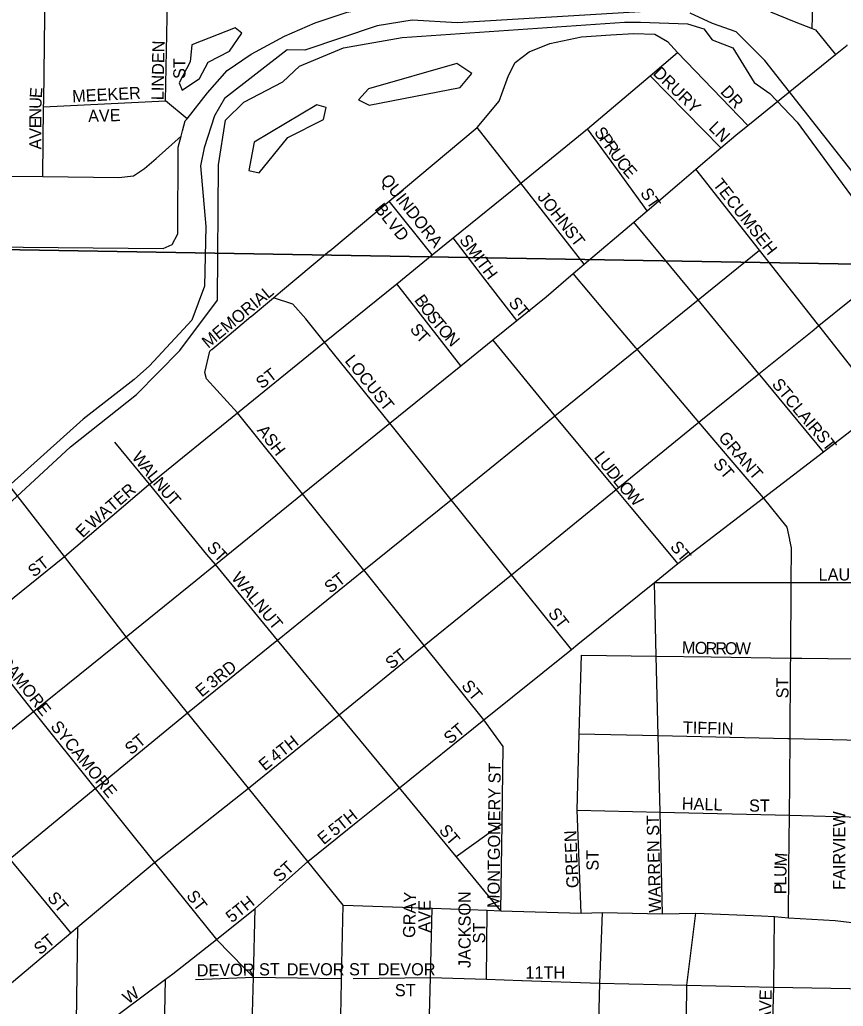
# Model space of a CAD drawing. Extents: x -784 to 1375, y -225 to 440.
# Drawn here: x 295.68 to 308.9, y 352.51 to 368.36 of the extents above; entities that cross this region are included whole.
import ezdxf

# ---------------------------------------------------------------- set-up
doc = ezdxf.new("R2010")
doc.units = 0
for name, color, linetype in [('GM_X_City_Street', 7, 'Continuous'), ('GM_X_City_Street_Text', 7, 'Continuous'), ('GM_X_Major_River', 7, 'Continuous'), ('GM_X_Minor_Lake', 7, 'Continuous'), ('GM_X_Section', 7, 'Continuous'), ('GM_X_State_Route', 7, 'Continuous')]:
    doc.layers.add(name, color=color, linetype=linetype)

msp = doc.modelspace()

# ---------------------------------------------------------------- linework, layer by layer
at = {"layer": 'GM_X_City_Street'}
for points in [[(308.402, 368.215), (308.442, 369.57), (308.493, 371.283), (308.546, 373.085)], [(296.062, 367.039), (296.08, 368.416), (296.099, 369.84), (296.099, 369.84)], [(298.364, 366.766), (298.018, 367.055), (298.043, 368.394), (298.046, 368.496), (298.079, 369.827)], [(298.294, 366.575), (298.336, 366.731), (298.364, 366.766), (298.695, 367.183), (299.011, 367.541), (299.395, 367.804), (299.928, 368.093), (300.42, 368.306), (300.934, 368.478), (301.391, 368.566), (301.904, 368.699), (302.405, 368.699), (302.976, 368.674), (303.39, 368.669), (303.86, 368.662), (304.548, 368.706), (304.949, 368.752), (305.288, 368.791), (306.151, 368.732), (307.184, 368.724)], [(307.733, 368.484), (308.114, 368.327), (308.402, 368.215), (308.457, 368.194), (308.777, 367.798)], [(308.429, 363.378), (308.434, 363.382), (308.511, 363.444), (311.105, 365.533), (314.482, 368.251)], [(300.654, 364.645), (300.655, 364.646), (301.609, 365.444), (303.022, 366.626), (303.377, 367.048), (303.528, 367.46), (303.635, 367.669), (303.859, 367.844), (304.193, 367.977), (304.698, 368.083), (305.17, 368.112), (305.54, 368.135), (305.876, 368.123), (306.079, 368.008), (306.24, 367.829), (307.368, 366.657)], [(304.798, 366.603), (305.801, 367.456), (306.24, 367.829)], [(306.938, 366.298), (305.801, 367.456)], [(296.046, 365.838), (296.061, 366.958), (296.062, 367.038), (296.062, 367.039)], [(296.061, 366.958), (298.018, 367.055)], [(297.775, 360.907), (299.175, 362.043), (300.574, 363.177), (301.733, 364.117), (302.303, 364.58), (302.637, 364.851), (303.723, 365.732), (304.798, 366.603)], [(303.76, 365.685), (303.723, 365.732), (303.022, 366.626)], [(305.275, 365.945), (304.798, 366.603)], [(293.48, 364.725), (297.983, 364.681), (298.126, 364.747), (298.217, 364.916), (298.222, 366.312), (298.27, 366.488), (298.293, 366.571), (298.294, 366.575)], [(294.649, 365.855), (294.701, 365.854), (294.841, 365.852), (296.046, 365.838), (297.267, 365.824), (297.503, 365.848), (297.679, 365.968), (297.871, 366.126), (298.27, 366.488)], [(308.491, 363.47), (308.491, 363.47), (307.56, 364.654), (306.537, 365.956)], [(305.751, 365.287), (305.275, 365.945), (305.275, 365.945)], [(304.744, 364.429), (303.76, 365.685), (303.76, 365.685)], [(302.303, 364.58), (301.609, 365.444)], [(307.061, 363.261), (306.571, 363.855), (305.538, 365.106)], [(303.149, 364.188), (302.637, 364.851)], [(299.808, 358.384), (299.818, 358.392), (301.204, 359.513), (302.605, 360.647), (304.271, 361.994), (305.592, 363.063), (306.571, 363.855), (307.56, 364.654)], [(299.864, 363.984), (299.866, 363.986), (300.654, 364.645)], [(305.07, 363.681), (304.566, 364.278)], [(302.246, 363.457), (301.733, 364.117)], [(303.66, 363.526), (303.149, 364.188), (303.149, 364.188)], [(299.391, 363.587), (299.393, 363.589), (299.754, 363.891), (299.864, 363.984)], [(300.628, 363.109), (300.626, 363.112), (300.574, 363.177), (300.273, 363.552), (300.061, 363.786), (299.754, 363.891)], [(298.759, 363.059), (298.762, 363.061), (299.391, 363.587)], [(305.574, 363.084), (305.07, 363.681), (305.07, 363.681)], [(302.759, 362.796), (302.246, 363.457), (302.246, 363.457)], [(309.533, 362.144), (308.511, 363.444), (308.491, 363.47)], [(300.81, 357.19), (302.175, 358.302), (303.573, 359.441), (305.255, 360.81), (306.582, 361.891), (306.618, 361.92), (307.549, 362.67), (308.429, 363.378)], [(307.569, 362.645), (307.549, 362.67), (307.061, 363.261), (307.061, 363.261)], [(304.536, 358.242), (303.573, 359.441), (302.605, 360.647), (301.62, 361.874), (300.628, 363.109)], [(304.259, 362.01), (303.276, 363.215)], [(299.175, 362.043), (298.677, 362.59), (298.649, 362.692), (298.73, 363.035), (298.759, 363.059)], [(306.582, 361.891), (305.592, 363.063), (305.574, 363.084), (305.574, 363.084)], [(308.584, 361.415), (307.569, 362.645), (307.569, 362.645)], [(301.217, 359.497), (301.204, 359.513), (300.22, 360.739), (299.175, 362.043)], [(305.501, 360.516), (305.496, 360.521), (305.255, 360.81), (304.271, 361.994), (304.259, 362.01), (304.259, 362.01)], [(304.642, 358.327), (305.871, 359.317), (306.248, 359.621), (307.622, 360.677), (308.584, 361.415), (309.147, 361.848), (309.533, 362.144)], [(307.102, 361.284), (306.582, 361.891)], [(297.609, 361.078), (297.609, 361.078), (297.205, 361.569)], [(307.622, 360.677), (307.102, 361.284), (307.102, 361.284)], [(298.819, 359.604), (298.684, 359.768), (297.759, 360.894), (297.609, 361.078)], [(296.399, 359.735), (297.746, 360.884), (297.759, 360.894), (297.775, 360.907)], [(308.045, 360.005), (308.002, 360.205), (307.622, 360.677)], [(306.248, 359.621), (305.501, 360.516)], [(308.057, 357.982), (308.058, 358.102), (308.068, 359.317), (308.073, 359.874), (308.046, 359.998), (308.045, 360.005)], [(294.796, 358.441), (294.886, 358.517), (296.399, 359.735)], [(303.404, 354.044), (302.685, 354.916), (301.775, 356.019), (300.81, 357.19), (299.818, 358.392), (298.819, 359.604)], [(302.11, 358.384), (301.217, 359.497), (301.217, 359.497)], [(305.871, 359.317), (307.97, 359.317), (307.97, 359.317)], [(306, 353.991), (305.96, 355.625), (305.931, 356.858), (305.9, 358.132), (305.871, 359.317)], [(307.97, 359.317), (308.068, 359.317), (309.859, 359.316)], [(295.898, 357.244), (294.886, 358.517)], [(298.374, 357.224), (299.808, 358.384)], [(303.131, 357.111), (302.175, 358.302), (302.11, 358.384), (302.11, 358.384)], [(301.75, 355.999), (301.775, 356.019), (303.131, 357.111), (304.536, 358.242), (304.642, 358.327), (304.642, 358.327)], [(304.691, 354.005), (304.627, 355.657), (304.663, 356.887), (304.7, 358.148)], [(304.7, 358.148), (305.9, 358.132), (306.78, 358.12), (306.78, 358.12)], [(306.78, 358.12), (308.058, 358.102), (308.237, 358.1), (308.237, 358.1)], [(308.237, 358.1), (310.733, 358.066)], [(308.042, 356.159), (308.048, 356.81), (308.057, 357.948), (308.057, 357.982)], [(296.496, 353.687), (295.518, 354.877), (294.501, 356.117), (293.494, 357.343)], [(295.898, 357.244), (296.891, 356.006), (297.844, 354.818), (298.835, 353.583), (299.286, 353.123)], [(296.96, 356.062), (298.374, 357.224)], [(299.354, 356.01), (300.81, 357.19)], [(303.404, 354.044), (303.424, 355.444), (303.441, 356.682), (303.131, 357.111)], [(304.663, 356.887), (305.931, 356.858), (308.014, 356.811), (308.014, 356.811)], [(308.014, 356.811), (308.048, 356.81), (309.187, 356.785), (310.946, 356.745)], [(308.031, 354.741), (308.037, 355.576), (308.042, 356.104), (308.042, 356.159)], [(292.554, 353.006), (293.277, 353.035), (294.223, 353.813), (295.518, 354.877), (296.891, 356.006), (296.958, 356.06), (296.96, 356.062)], [(293.82, 351.442), (294.658, 352.146), (295.198, 352.598), (296.496, 353.687), (296.611, 353.783), (297.844, 354.818), (299.354, 356.01)], [(301.107, 355.481), (301.749, 355.998), (301.75, 355.999)], [(304.627, 355.657), (305.96, 355.625), (308.037, 355.576), (309.19, 355.548)], [(300.303, 354.834), (301.107, 355.481), (301.107, 355.481)], [(302.685, 354.916), (303.424, 355.444)], [(296.585, 351.875), (298.02, 352.944), (298.138, 353.027), (298.835, 353.583), (299.456, 354.078), (300.303, 354.834)], [(308.024, 353.931), (308.03, 354.67), (308.031, 354.741)], [(298.958, 333.384), (298.958, 333.385), (298.963, 333.583), (299.009, 335.502), (299.057, 337.477), (299.117, 339.989), (299.149, 341.322), (299.211, 343.901), (299.26, 345.904), (299.318, 348.338), (299.339, 349.198), (299.375, 350.7), (299.402, 351.82), (299.43, 352.976), (299.456, 354.078)], [(302.172, 348.778), (302.201, 349.994), (302.217, 350.66), (302.235, 351.404), (302.244, 351.764), (302.273, 352.97), (302.3, 354.083)], [(303.173, 352.942), (303.184, 354.052)], [(304.886, 348.487), (304.887, 348.56), (304.922, 349.957), (304.958, 351.406), (304.994, 352.879), (305.035, 354.013)], [(306.392, 352.79), (306.393, 352.848), (306.535, 354.002)], [(307.7, 349.84), (307.703, 349.939), (307.745, 351.382), (307.788, 352.818), (307.797, 353.948)], [(296.184, 333.611), (296.218, 335.587), (296.251, 337.52), (296.294, 340.026), (296.317, 341.377), (296.361, 343.955), (296.374, 344.723), (296.394, 345.899), (296.418, 347.269), (296.434, 348.201), (296.482, 348.524), (296.522, 348.791), (296.545, 348.943), (296.554, 349.611), (296.556, 349.714), (296.569, 350.739), (296.58, 351.531), (296.585, 351.875), (296.611, 353.783)], [(299.286, 353.123), (299.43, 352.976), (300.845, 352.955)], [(298.5, 352.939), (299.43, 352.976)], [(301.031, 352.957), (302.273, 352.97)], [(302.273, 352.97), (303.173, 352.942), (303.739, 352.922)], [(297.934, 348.991), (297.934, 348.992), (297.943, 349.405), (297.972, 350.719), (297.996, 351.848), (298.02, 352.944)], [(303.739, 352.922), (303.745, 352.922), (304.994, 352.879), (306.393, 352.848), (307.788, 352.818), (309.007, 352.792), (310.275, 352.764)], [(306.305, 348.315), (306.307, 348.444), (306.337, 349.948), (306.365, 351.394), (306.391, 352.724), (306.392, 352.79)]]:
    msp.add_lwpolyline(points, dxfattribs=at)
at = {"layer": 'GM_X_Major_River'}
for points in [[(305.73, 368.491), (302.701, 368.307), (301.98, 368.35), (301.415, 368.258), (300.256, 367.869), (299.974, 367.874), (298.965, 367.091), (298.803, 366.811), (298.638, 366.297), (298.578, 366.008), (298.664, 365.034), (298.647, 364.078), (298.442, 363.532), (297.763, 362.798), (297.517, 362.575), (296.698, 361.938), (295.489, 360.853)], [(306.803, 368.299), (306.443, 368.464)], [(292.8, 358.173), (293.092, 358.211), (293.764, 358.521), (293.996, 358.776), (294.117, 359.017), (294.285, 359.226), (294.956, 359.968), (295.125, 360.231), (296.495, 361.495), (297.552, 362.339), (298.246, 363.041), (298.855, 363.854), (298.868, 366.026), (298.982, 366.746), (299.277, 367.031), (299.902, 367.358), (300.173, 367.612), (300.876, 367.906), (301.819, 368.071), (305.39, 368.317), (305.648, 368.32), (306.4, 368.292), (306.666, 368.209), (306.797, 368.034)], [(321.839, 353.708), (321.346, 353.365), (320.794, 353.234), (320.542, 353.184), (320.024, 353.233), (314.199, 354.945), (313.484, 355.326), (312.452, 356.035), (312.259, 356.187), (312.065, 356.332), (311.314, 357.324), (311.248, 357.576), (311.253, 357.827), (311.365, 358.358), (312.29, 359.116), (312.616, 359.353), (312.74, 359.641), (312.946, 360.193), (312.717, 360.98), (310.168, 364.489), (307.645, 367.7), (307.182, 368.163), (306.803, 368.299)], [(306.797, 368.034), (307.13, 367.905), (307.473, 367.351), (307.721, 367.174), (308.16, 366.711), (312.724, 360.495)]]:
    msp.add_lwpolyline(points, dxfattribs=at)
at = {"layer": 'GM_X_Minor_Lake'}
for points in [[(299.243, 368.141), (299.135, 368.229), (298.443, 367.955), (298.416, 367.681), (298.24, 367.346), (298.285, 367.228)], [(298.285, 367.228), (298.562, 367.413), (298.706, 367.677), (299.044, 367.854), (299.243, 368.141)], [(302.939, 367.492), (302.698, 367.652), (301.276, 367.246)], [(301.276, 367.246), (301.117, 367.068), (301.289, 366.987), (302.748, 367.267), (302.939, 367.492)], [(300.451, 366.99), (299.442, 366.391), (299.358, 365.937), (299.522, 365.896)], [(299.522, 365.896), (299.983, 366.463), (300.558, 366.753), (300.599, 366.949), (300.451, 366.99)]]:
    msp.add_lwpolyline(points, dxfattribs=at)
at = {"layer": 'GM_X_Section'}
for points in [[(293.747, 385.447), (314.846, 385.028), (314.451, 364.338), (293.485, 364.699)], [(293.485, 364.699), (314.451, 364.338), (313.882, 343.598), (293.008, 344.097)]]:
    msp.add_lwpolyline(points, close=True, dxfattribs=at)
at = {"layer": 'GM_X_State_Route'}
for points in [[(308.329, 367.435), (308.777, 367.798), (308.966, 367.951), (308.967, 367.952)], [(306.275, 365.733), (306.537, 365.956), (306.938, 366.298), (307.179, 366.503), (307.368, 366.657), (308.327, 367.434), (308.329, 367.435)], [(298.504, 359.349), (298.819, 359.604), (300.22, 360.739), (301.62, 361.874), (302.759, 362.796), (303.276, 363.215), (303.66, 363.526), (304.131, 363.907), (304.566, 364.278), (304.744, 364.429), (305.538, 365.106), (305.751, 365.287), (306.272, 365.731), (306.275, 365.733)], [(297.388, 358.445), (296.399, 359.735), (295.013, 361.506), (293.695, 363.164), (293.561, 363.265), (293.458, 363.284)], [(297.388, 358.445), (298.504, 359.349), (298.504, 359.349)], [(293.404, 355.233), (294.501, 356.117), (295.898, 357.244), (297.388, 358.445)], [(300.869, 354.134), (300.869, 354.134), (300.303, 354.834), (299.354, 356.01), (298.374, 357.224), (297.388, 358.445)], [(300.844, 352.905), (300.845, 352.955), (300.869, 354.134)], [(300.869, 354.134), (302.3, 354.083), (303.184, 354.052), (303.404, 354.044), (304.691, 354.005), (305.035, 354.013), (306, 353.991)], [(306, 353.991), (306.535, 354.002), (307.588, 353.96), (307.797, 353.948), (308.024, 353.931), (308.77, 353.888), (309.936, 353.745), (309.947, 353.744), (310.308, 353.688), (312.658, 353.382), (313.321, 353.297), (314.184, 353.183), (314.388, 353.157)], [(300.753, 348.399), (300.753, 348.403), (300.764, 348.987), (300.799, 350.68), (300.822, 351.792), (300.844, 352.905)]]:
    msp.add_lwpolyline(points, dxfattribs=at)

# ---------------------------------------------------------------- texts
at = {"layer": 'GM_X_City_Street_Text'}
for s, height, rotation, p in [('LINDEN', 0.1953, 88.9197, (297.986, 367.063)), ('ST', 0.1953, 90, (298.339, 367.406)), ('DRURY', 0.1953, 315.8299, (305.834, 367.484)), ('E', 0.195, 85.9942, (296.031, 367.093)), ('MEEKER', 0.1953, 3.0111, (296.525, 367.03)), ('DR', 0.1953, 312.8801, (306.918, 367.191)), ('U', 0.195, 88.5684, (296.027, 366.924)), ('N', 0.195, 89.9703, (296.027, 366.753)), ('AVE', 0.1953, 1.9738, (296.778, 366.712)), ('E', 0.195, 89.9707, (296.027, 366.615)), ('V', 0.195, 89.9703, (296.027, 366.444)), ('S', 0.195, 305.2741, (304.893, 366.551)), ('LN', 0.1953, 315, (306.728, 366.607)), ('A', 0.195, 89.9672, (296.027, 366.272)), ('P', 0.195, 305.2685, (304.973, 366.439)), ('R', 0.195, 305.2632, (305.052, 366.326)), ('U', 0.195, 305.2695, (305.142, 366.2)), ('C', 0.195, 307.5942, (305.246, 366.053)), ('E', 0.195, 311.293, (305.349, 365.92)), ('QUINDORA', 0.1953, 308.419, (301.46, 365.78)), ('TECUMSEH', 0.1953, 308.0721, (306.8, 365.71)), ('ST', 0.1953, 304.6936, (305.633, 365.571)), ('JOHN', 0.1953, 308.1565, (303.981, 365.504)), ('BLVD', 0.1953, 308.6611, (301.367, 365.314)), ('ST', 0.1953, 307.5682, (304.411, 364.954)), ('SMITH', 0.1953, 306.6072, (302.727, 364.816)), ('MEMORIAL', 0.1953, 39.7098, (298.704, 363.069)), ('B', 0.195, 306.0832, (302.006, 363.853)), ('ST', 0.1953, 309.8038, (303.517, 363.803)), ('O', 0.195, 306.1009, (302.097, 363.728)), ('S', 0.195, 306.974, (302.2, 363.586)), ('T', 0.195, 309.9966, (302.29, 363.468)), ('S', 0.195, 305.7989, (301.934, 363.389)), ('O', 0.195, 310.7755, (302.38, 363.36)), ('T', 0.195, 313.1395, (302.032, 363.256)), ('N', 0.195, 310.8232, (302.492, 363.23)), ('LOCUST', 0.1953, 308.9907, (300.887, 362.875)), ('ST', 0.1953, 37.5629, (299.564, 362.417)), ('ST', 0.1953, 309.8011, (307.745, 362.497)), ('CLAIR', 0.1953, 310.1541, (307.951, 362.239)), ('ASH', 0.1953, 307.689, (299.478, 361.757)), ('GRANT', 0.1953, 310.7298, (306.885, 361.638)), ('ST', 0.1953, 307.5682, (308.45, 361.671)), ('W', 0.195, 308.3966, (297.467, 361.327)), ('L', 0.195, 308.4603, (304.892, 361.327)), ('A', 0.195, 308.398, (297.606, 361.152)), ('U', 0.195, 308.4482, (304.978, 361.22)), ('ST', 0.1953, 310.2345, (306.801, 361.214)), ('L', 0.195, 309.0015, (297.714, 361.016)), ('D', 0.195, 308.4525, (305.085, 361.085)), ('L', 0.195, 308.9373, (305.193, 360.949)), ('WATER', 0.1953, 40.8562, (296.847, 360.164)), ('N', 0.195, 310.8033, (297.805, 360.904)), ('U', 0.195, 311.1937, (297.918, 360.773)), ('O', 0.195, 311.1334, (305.284, 360.836)), ('T', 0.195, 311.1962, (298.031, 360.643)), ('W', 0.195, 311.8032, (305.399, 360.705)), ('E', 0.195, 45, (296.691, 360.024)), ('ST', 0.1953, 312.5072, (298.669, 359.869)), ('ST', 0.1953, 309.8038, (306.112, 359.884)), ('ST', 0.1953, 37.5649, (295.903, 359.392)), ('WALNUT', 0.1953, 309.5589, (299.065, 359.386)), ('ST', 0.1953, 37.5629, (300.664, 359.134)), ('LAUREL', 0.1953, 0, (308.507, 359.348)), ('ST', 0.1953, 307.5682, (304.153, 358.818)), ('SYCAMORE', 0.1953, 308.6594, (295.112, 358.32)), ('M', 0.195, 357.9778, (306.308, 358.179)), ('O', 0.195, 357.9915, (306.515, 358.172)), ('R', 0.195, 358.7378, (306.689, 358.165)), ('R', 0.195, 359.8991, (306.848, 358.162)), ('O', 0.195, 359.9956, (307.003, 358.162)), ('W', 0.195, 0, (307.175, 358.162)), ('ST', 0.1953, 37.5755, (301.644, 357.913)), ('3RD', 0.1953, 38.6585, (298.773, 357.604)), ('E', 0.195, 39.7921, (298.601, 357.466)), ('ST', 0.1953, 309.8011, (302.76, 357.65)), ('ST', 0.1953, 90, (308.023, 357.455)), ('SYCAMORE', 0.1953, 309.2366, (296.161, 356.997)), ('TIFFIN', 0.1953, 358.6685, (306.325, 356.89)), ('ST', 0.1953, 39.8114, (302.588, 356.709)), ('ST', 0.1953, 39.8006, (297.466, 356.538)), ('4TH', 0.1953, 38.2889, (299.787, 356.418)), ('E', 0.195, 39.7921, (299.615, 356.28)), ('MONTGOMERY ST', 0.19531, 89.5267, (303.383, 354.086)), ('HALL', 0.1953, 358.4527, (306.308, 355.669)), ('ST', 0.1953, 0, (307.39, 355.635)), ('5TH', 0.1953, 38.2889, (300.733, 355.232)), ('WARREN ST', 0.1953, 91.432, (305.978, 354.016)), ('FAIRVIEW', 0.1953, 90, (308.934, 354.378)), ('E', 0.195, 39.7921, (300.56, 355.094)), ('ST', 0.1953, 309.8011, (302.399, 355.33)), ('GREEN', 0.1953, 92.4893, (304.655, 354.411)), ('ST', 0.1953, 90, (304.974, 354.687)), ('ST', 0.1953, 42.5045, (299.854, 354.491)), ('M', 0.195, 86.6327, (307.992, 354.753)), ('U', 0.195, 89.2295, (307.989, 354.584)), ('L', 0.195, 89.9495, (307.989, 354.447)), ('P', 0.195, 89.9453, (307.989, 354.309)), ('ST', 0.1953, 310.2345, (296.109, 354.247)), ('ST', 0.1953, 307.5656, (298.344, 354.28)), ('5TH', 0.1953, 38.6571, (299.083, 353.84)), ('GRAY', 0.1953, 88.5321, (302.025, 353.604)), ('JACKSON', 0.1953, 90, (302.919, 353.123)), ('AVE', 0.1953, 90, (302.275, 353.691)), ('ST', 0.1953, 90, (303.152, 353.519)), ('ST', 0.1953, 39.8006, (296.005, 353.324)), ('DEVOR ST', 0.1953, 0.8421, (298.521, 352.988)), ('DEVOR ST', 0.1953, 0, (299.965, 353.005)), ('DEVOR', 0.1953, 0, (301.426, 353.005)), ('11TH', 0.1953, 0, (303.798, 352.954)), ('W', 0.195, 34.9913, (297.417, 352.535)), ('ST', 0.1953, 0, (301.701, 352.669)), ('ANDERSON AVE', 0.19531, 88.4087, (307.697, 350.701))]:
    msp.add_text(s, height=height, rotation=rotation, dxfattribs=at).set_placement(p)

doc.saveas('drawing.dxf')
